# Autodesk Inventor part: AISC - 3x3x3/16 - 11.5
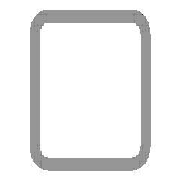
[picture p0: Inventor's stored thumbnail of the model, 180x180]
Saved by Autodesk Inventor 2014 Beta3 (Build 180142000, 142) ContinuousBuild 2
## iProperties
IsCustomPart: 1
Created: 2011-01
Part Number: AISC - 3x3x3/16 - 11.5
Material: Steel, Mild
Description: Tube
Document SubType Name: Modeling
Standard: ANSI
Designer: Beta-8540w
Standards Organization: ANSI
Language: en-US
Size Designation: 3x3x3/16
Categories: <MemberInstance><Categories><Category DisplayName="Structural Shapes" InternalName="089c4875-fa83-4c05-b084-43b9cc11f5ed" Mnemonic="GRDR"><CategoryParameter Dis
Stock Number: 3x3x3/16
Density: 7.86 g/cm^3
Appearance: Steel
_CCFamilyMember: 9
_CCFamilyDisplayName: ANSI AISC (Square) - Tube
_FrameMemberDoc: Frame Member File
_Version: 15.0.0
_GetPNFromCC: 1
G_L: 11.500 in
G_W: 3.000 in
G_H: 3.000 in
Author: Beta-8540w
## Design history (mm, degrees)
node "Start plane"
node "End plane"
sketch "Sketch"
  geometry: L1 (-38.1, -28.575)-(-38.1, 28.575); L2 (-28.575, 38.1)-(28.575, 38.1); L3 (38.1, 28.575)-(38.1, -28.575); L4 (28.575, -38.1)-(-28.575, -38.1); L5 (-28.575, 33.337)-(28.575, 33.338); L6 (33.338, 28.575)-(33.338, -28.575); L7 (28.575, -33.337)-(-28.575, -33.338); L8 (-33.338, -28.575)-(-33.338, 28.575); L9 (0, 56.102)-(0, -56.102) reference; L10 (-56.102, 0)-(56.102, 0) reference; A1 r 9.525 centre (-28.575, -28.575) between (-38.1, -28.575) and (-28.575, -38.1); A2 r 9.525 centre (-28.575, 28.575) between (-28.575, 38.1) and (-38.1, 28.575); A3 r 9.525 centre (28.575, 28.575) between (38.1, 28.575) and (28.575, 38.1); A4 r 9.525 centre (28.575, -28.575) between (28.575, -38.1) and (38.1, -28.575); A5 r 4.763 centre (-28.575, 28.575) between (-28.575, 33.337) and (-33.338, 28.575); A6 r 4.763 centre (28.575, 28.575) between (33.338, 28.575) and (28.575, 33.338); A7 r 4.763 centre (28.575, -28.575) between (28.575, -33.337) and (33.338, -28.575); A8 r 4.763 centre (-28.575, -28.575) between (-33.338, -28.575) and (-28.575, -33.338)
  constraints: 16 end point, 16 point on circle, 8 centre point, 8 tangent, 4 parallel, 3 equal radius, 2 perpendicular, 7 other
  dimensions: "d10" = 76.2 distance between parallel lines of L2 L4 (= G_H); "d11" = 76.2 distance between parallel lines of L1 L3 (= G_W); "d12" = 4.7625 distance between parallel lines of L3 L6 (= G_T); "d15" = 38.1 distance between parallel lines of L2 L10 (= 0.5 x d10); "d16" = 38.1 distance between parallel lines of L9 L3 (= 0.5 x d11); "d17" = 9.525 radius of A1 (= G_IR)
extrude "Body" new body sketch "Sketch" stored distance "d3" = 292.1 (= G_L); taper "d4" = 0 deg
node "Driven Length"
  sketch "Sketch3"
    geometry: L1 (0, 0)-(10, 0) reference
    constraints: 2 end point, 1 horizontal
  workplane "Work Plane3"
  sketch "Sketch4"
    geometry: L1 (-2, -38.1)-(12, -38.1) reference; L2 (-2, 254)-(12, 254) reference
    dimensions: "d19" = 292.1 distance between parallel lines of L1 L2 (derived)
workplane "Work Plane4"
split "Split1"
body "Solid1"
other parameters: "G_W" = 76.2 [user parameter; used in 1 equation term], "G_H" = 76.2 [user parameter; used in 1 equation term], "G_T" = 4.7625 [user parameter; used in 1 equation term], "G_IR" = 9.525 [user parameter; used in 1 equation term], "G_L" = 292.1 (= d19) [user parameter; used in 1 equation term], "G_OFFSET_START" = 38.1 [user parameter; used in 1 equation term], "G_OFFSET_END" = 0 [user parameter; used in 1 equation term], "d13" = -38.1 (= -G_OFFSET_START), "d14" = 254 (= G_OFFSET_END + B_L), "B_L" = 254 [user parameter; used in 1 equation term], "d18" = 90 deg
